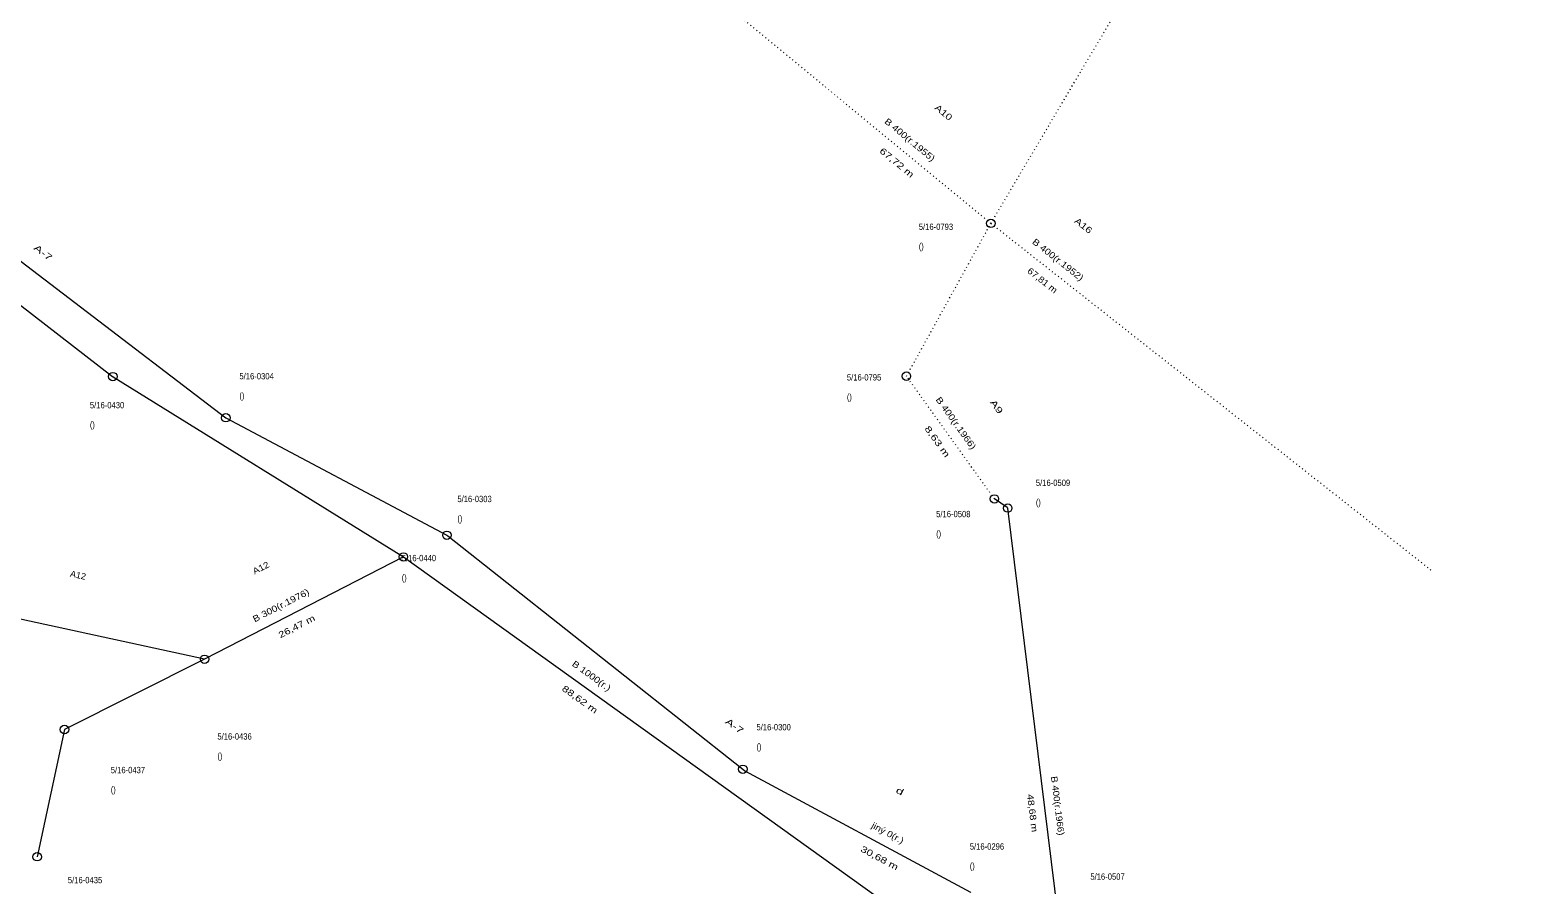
# Model space of a CAD drawing. Extents: x -710854 to -709799, y -1117012 to -1115891.
# Drawn here: x -710384 to -710205.5, y -1116601.8 to -1116500.5 of the extents above; entities that cross this region are included whole.
import ezdxf
from ezdxf.enums import TextEntityAlignment as Align

# ---------------------------------------------------------------- set-up
doc = ezdxf.new("R2010")
doc.units = 0
doc.header["$LTSCALE"] = 0.3
doc.linetypes.add('DOTTED', pattern=[1.5, 0.3, -1.2])
for name, color, linetype, lineweight in [('36', 7, 'Continuous', 13), ('38', 7, 'Continuous', 13), ('44', 7, 'Continuous', 13)]:
    doc.layers.add(name, color=color, linetype=linetype, lineweight=lineweight)
doc.layers.add('48', color=7, linetype='Continuous')

msp = doc.modelspace()

# ---------------------------------------------------------------- linework, layer by layer
at = {"layer": '36'}
msp.add_line((-710360.82, -1116546.41), (-710334.649, -1116560.338), dxfattribs=at)
for points in [[(-710396.742, -1116519.013), (-710396.602, -1116519.097), (-710360.82, -1116546.41)], [(-710334.649, -1116560.338), (-710334.547, -1116560.393), (-710299.622, -1116588.059)], [(-710299.622, -1116588.059), (-710299.384, -1116588.249), (-710272.66, -1116602.62), (-710272.639, -1116602.644)]]:
    msp.add_lwpolyline(points, dxfattribs=at)
at = {"layer": '38', "linetype": 'DOTTED'}
for p, q in [((-710270.252, -1116523.383), (-710323.32, -1116479.62)), ((-710280.249, -1116541.492), (-710270.252, -1116523.383)), ((-710270.252, -1116523.383), (-710217.938, -1116564.631)), ((-710269.84, -1116556.03), (-710280.249, -1116541.492))]:
    msp.add_line(p, q, dxfattribs=at)
at = {"layer": '38'}
for p, q in [((-710262.27, -1116605.42), (-710268.259, -1116557.114)), ((-710339.8, -1116562.9), (-710267.796, -1116614.57))]:
    msp.add_line(p, q, dxfattribs=at)
at = {"layer": '38', "linetype": 'DOTTED'}
msp.add_lwpolyline([(-710270.252, -1116523.383), (-710205.501, -1116413.93), (-710237.235, -1116397.005)], dxfattribs=at)
at = {"layer": '38'}
for points in [[(-710398.3, -1116522.9), (-710374.23, -1116541.52), (-710374.197, -1116541.54)], [(-710374.197, -1116541.54), (-710374.159, -1116541.564), (-710339.8, -1116562.9)], [(-710268.259, -1116557.114), (-710268.26, -1116557.11), (-710268.328, -1116557.064), (-710269.84, -1116556.03)], [(-710339.8, -1116562.9), (-710363.33, -1116575.03), (-710379.92, -1116583.35)], [(-710363.33, -1116575.03), (-710392.833, -1116568.639), (-710393.06, -1116568.59)], [(-710379.92, -1116583.35), (-710379.923, -1116583.362), (-710383.16, -1116598.43)]]:
    msp.add_lwpolyline(points, dxfattribs=at)
at = {"layer": '44'}
for centre in [(-710270.252, -1116523.383), (-710374.197, -1116541.54), (-710280.249, -1116541.492), (-710360.82, -1116546.41), (-710269.84, -1116556.03), (-710268.259, -1116557.114), (-710334.649, -1116560.338), (-710339.8, -1116562.9), (-710363.33, -1116575.03), (-710379.92, -1116583.35), (-710299.622, -1116588.059), (-710383.16, -1116598.43)]:
    msp.add_circle(centre, 0.5, dxfattribs=at)

# ---------------------------------------------------------------- texts
at = {"layer": '48'}
for s, rotation, width, p in [('A10', 320.49, 1.3, (-710276.0871, -1116510.5333)), ('B 400(r.1955)', 320.49, 1.2, (-710280.0816, -1116513.7743)), ('67,72 m', 320.49, 1.35, (-710281.6236, -1116516.4809)), ('A16', 321.75, 1.3, (-710259.5287, -1116523.9419)), ('A-7', 322.28, 1.55, (-710382.6779, -1116527.147)), ('B 400(r.1952)', 321.75, 1.2, (-710262.5417, -1116527.9849)), ('67,81 m', 321.75, 1.15, (-710264.3817, -1116530.4434)), ('B 400(r.1966)', 305.6, 1.2, (-710274.6855, -1116547.2692)), ('A9', 305.6, 1.45, (-710269.8785, -1116545.3252)), ('8,63 m', 305.6, 1.4, (-710276.8977, -1116549.4542)), ('A12', 27.27, 1.15, (-710356.4983, -1116564.5332)), ('A12', 347.78, 1.05, (-710378.3899, -1116565.4244)), ('B 300(r.1976)', 27.27, 1.2, (-710354.1183, -1116568.9755)), ('26,47 m', 27.27, 1.3, (-710352.2588, -1116571.4716)), ('B 1000(r.)', 324.34, 1.2, (-710317.7416, -1116577.3009)), ('88,62 m', 324.34, 1.35, (-710319.1251, -1116580.0867)), ('A-7', 324.34, 1.5, (-710300.8171, -1116583.2428)), ('d', 331.73, 1.6, (-710281.2006, -1116590.9876)), ('B 400(r.1966)', 277.07, 1.15, (-710262.7113, -1116592.4348)), ('48,68 m', 277.07, 1.25, (-710265.6974, -1116593.2963)), ('jiný 0(r.)', 331.73, 1.15, (-710282.6376, -1116595.9374)), ('30,68 m', 331.73, 1.35, (-710283.6066, -1116598.9014))]:
    msp.add_text(s, height=0.75, rotation=rotation, dxfattribs=dict(at, width=width)).set_placement(p, align=Align.CENTER)
for s, width, p in [('5/16-0793', 0.9, (-710278.786, -1116524.161)), ('()', 0.7, (-710278.786, -1116526.471)), ('5/16-0304', 0.9, (-710359.209, -1116541.865)), ('5/16-0795', 0.9, (-710287.295, -1116542.002)), ('()', 0.7, (-710359.209, -1116544.175)), ('()', 0.7, (-710287.295, -1116544.312)), ('5/16-0430', 0.9, (-710376.913, -1116545.296)), ('()', 0.7, (-710376.913, -1116547.606)), ('5/16-0509', 0.9, (-710264.925, -1116554.491)), ('5/16-0303', 0.9, (-710333.408, -1116556.413)), ('()', 0.7, (-710264.925, -1116556.801)), ('()', 0.7, (-710333.408, -1116558.723)), ('5/16-0508', 0.9, (-710276.728, -1116558.197)), ('()', 0.7, (-710276.728, -1116560.507)), ('5/16-0440', 0.9, (-710339.995, -1116563.412)), ('()', 0.7, (-710339.995, -1116565.722)), ('5/16-0300', 0.9, (-710298, -1116583.449)), ('5/16-0436', 0.9, (-710361.816, -1116584.547)), ('()', 0.7, (-710298, -1116585.759)), ('()', 0.7, (-710361.816, -1116586.857)), ('5/16-0437', 0.9, (-710374.442, -1116588.527)), ('()', 0.7, (-710374.442, -1116590.837)), ('5/16-0296', 0.9, (-710272.748, -1116597.584)), ('()', 0.7, (-710272.748, -1116599.894)), ('5/16-0435', 0.9, (-710379.52, -1116601.564)), ('5/16-0507', 0.9, (-710258.475, -1116601.153))]:
    msp.add_text(s, height=0.75, dxfattribs=dict(at, width=width)).set_placement(p)

doc.saveas('drawing.dxf')
